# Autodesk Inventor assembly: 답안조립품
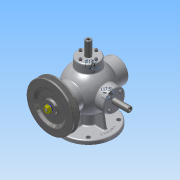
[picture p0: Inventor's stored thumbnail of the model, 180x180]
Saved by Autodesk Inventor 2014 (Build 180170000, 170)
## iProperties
Created: 2016-01
Part Number: 답안조립품
Document SubType Name: Assembly
Designer: Administrator
Mass: 3764.72 g
Surface Area: 2411.01 cm^2
Volume: 903.659 cm^3
Density: 4.16609 g/cm^3
Author: Administrator
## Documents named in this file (17)
- C:\Users\Administrator\Desktop\360108V1010\답안조립품.iam
- C:\Users\Administrator\Desktop\360108V1010\본체.ipt
- C:\Users\Administrator\Desktop\360108V1010\V-벨트풀리.ipt
- C:\Users\Administrator\Desktop\360108V1010\너트-M8x1.ipt
- C:\Users\Administrator\Desktop\360108V1010\뒤커버.ipt
- C:\Users\Administrator\Desktop\360108V1010\베어링- 6202.ipt
- C:\Users\Administrator\Desktop\360108V1010\본체커버.ipt
- C:\Users\Administrator\Desktop\360108V1010\볼트 M4x0.7.ipt
- C:\Users\Administrator\Desktop\360108V1010\스프링1.ipt
- C:\Users\Administrator\Desktop\360108V1010\스프링2.ipt
- C:\Users\Administrator\Desktop\360108V1010\슬라이드 커버.ipt
- C:\Users\Administrator\Desktop\360108V1010\슬라이드.ipt
- C:\Users\Administrator\Desktop\360108V1010\앞커버.ipt
- C:\Users\Administrator\Desktop\360108V1010\오일실.ipt
- C:\Users\Administrator\Desktop\360108V1010\와셔 8x17.ipt
- C:\Users\Administrator\Desktop\360108V1010\축.ipt
- C:\Users\Administrator\Desktop\360108V1010\키-4x4.ipt
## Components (18 placed, 2 different names)
1. V-벨트풀리:1 — 각도:2, 각도:4
2. M4x0.7x12:5
3. M4x0.7x12:2
4. M4x0.7x12:9
5. M4x0.7x12:10
6. M4x0.7x12:11
7. M4x0.7x12:4
8. M4x0.7x12:12
9. M4x0.7x12:13
10. M4x0.7x12:14
11. M4x0.7x12:3
12. M4x0.7x12:15
13. M4x0.7x12:16
14. M4x0.7x12:17
15. M4x0.7x12:1
16. M4x0.7x12:18
17. M4x0.7x12:19
18. M4x0.7x12:20
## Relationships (2: Angle 2)
- 각도:2 [Angle]: V-벨트풀리:1
- 각도:4 [Angle]: V-벨트풀리:1
